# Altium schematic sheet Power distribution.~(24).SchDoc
size A3; SheetNumber: 4; SheetTotal: 7
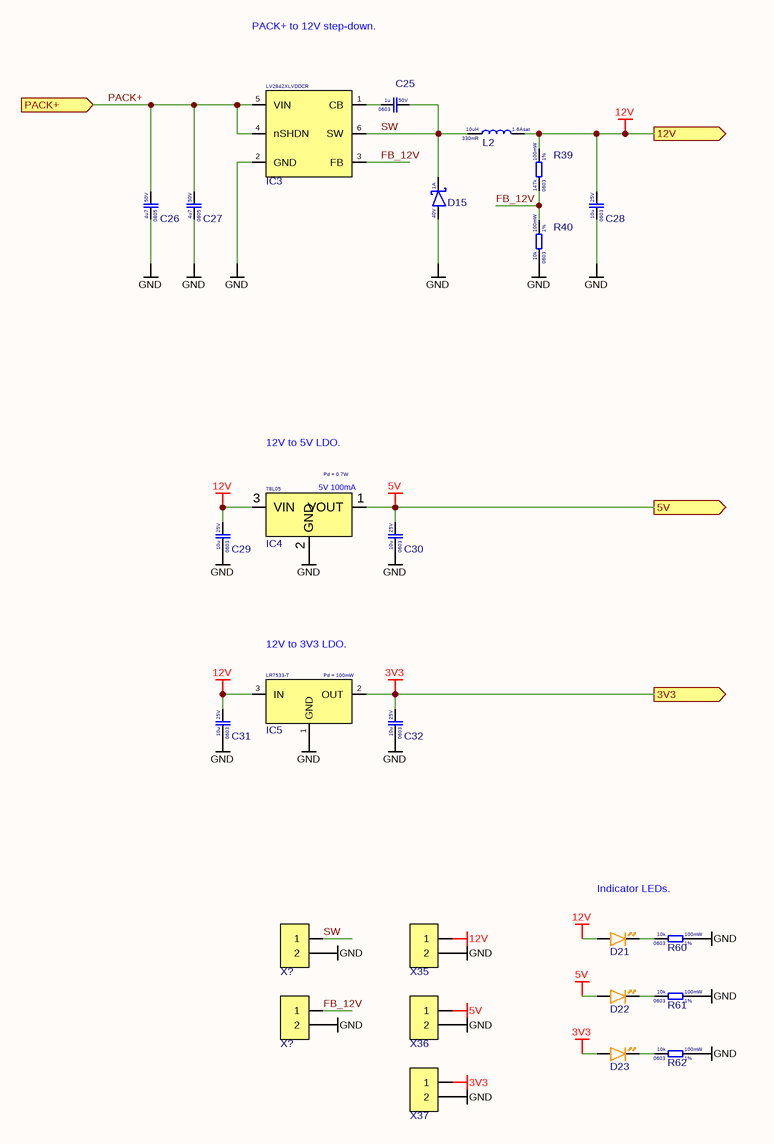
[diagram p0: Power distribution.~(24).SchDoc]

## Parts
(Parts that share a designator on the sheet are numbered #1, #2 ... from top to bottom, then left to right.)
C25  Voltage Rating: 50V  Case Code (Imperial): 0603  Capacitance: 1u  [CAP 0603]  (hidden comment: CL10A105KB8NNNC)
C26  Voltage Rating: 50V  Case Code (Imperial): 0805  Capacitance: 4u7  [Cap_0805]  (hidden comment: CL21A475KBQNNNE)
C27  Voltage Rating: 50V  Case Code (Imperial): 0805  Capacitance: 4u7  [Cap_0805]  (hidden comment: CL21A475KBQNNNE)
C28  Voltage Rating: 25V  Case Code (Imperial): 0603  Capacitance: 10u  [CAP 0603]  (hidden comment: CL10A106MA8NRNC)
C29  Voltage Rating: 25V  Case Code (Imperial): 0603  Capacitance: 10u  [CAP 0603]  (hidden comment: CL10A106MA8NRNC)
C30  Voltage Rating: 25V  Case Code (Imperial): 0603  Capacitance: 10u  [CAP 0603]  (hidden comment: CL10A106MA8NRNC)
C31  Voltage Rating: 25V  Case Code (Imperial): 0603  Capacitance: 10u  [CAP 0603]  (hidden comment: CL10A106MA8NRNC)
C32  Voltage Rating: 25V  Case Code (Imperial): 0603  Capacitance: 10u  [CAP 0603]  (hidden comment: CL10A106MA8NRNC)
D15  Forward Current: 1A  Reverse Voltage: 40V  [SOD-323]  (hidden comment: 1N5819WS)
D21  XL-1608UOC-06  [DIODE_0603]  (value not drawn)
D22  XL-1608UOC-06  [DIODE_0603]  (value not drawn)
D23  XL-1608UOC-06  [DIODE_0603]  (value not drawn)
IC3  LV2842XLVDDCR  [SOT-23-6]
IC4  Pd = 0.7W  [SOT-89-3]
IC5  Pd = 100mW  [SOT-23 123]
L2  Resistance: 330mR  Saturation current: 1.6Asat  Inductance: 10uH  [IND 1008]  (hidden comment: FTC252012S100MBCA)
R39  Resistance Tolerance: 1%  Resistance: 147k  Power Rating: 100mW  Case Code (Imperial): 0603  [RES_0603]  (hidden comment: 0603WAF1473T5E)
R40  Resistance Tolerance: 1%  Resistance: 10k  Power Rating: 100mW  Case Code (Imperial): 0603  [RES_0603]  (hidden comment: 0603WAF1002T5E)
R60  Resistance Tolerance: 1%  Resistance: 10k  Power Rating: 100mW  Case Code (Imperial): 0603  [RES_0603]  (hidden comment: 0603WAF1002T5E)
R61  Resistance Tolerance: 1%  Resistance: 10k  Power Rating: 100mW  Case Code (Imperial): 0603  [RES_0603]  (hidden comment: 0603WAF1002T5E)
R62  Resistance Tolerance: 1%  Resistance: 10k  Power Rating: 100mW  Case Code (Imperial): 0603  [RES_0603]  (hidden comment: 0603WAF1002T5E)
X35  ZX-PZ1.27-1-2PZZ  [Pin header 1x2 1.27mmP THT Vertical]  (value not drawn)
X36  ZX-PZ1.27-1-2PZZ  [Pin header 1x2 1.27mmP THT Vertical]  (value not drawn)
X37  ZX-PZ1.27-1-2PZZ  [Pin header 1x2 1.27mmP THT Vertical]  (value not drawn)
X?#1  ZX-PZ1.27-1-2PZZ  [Pin header 1x2 1.27mmP THT Vertical]  (value not drawn)
X?#2  ZX-PZ1.27-1-2PZZ  [Pin header 1x2 1.27mmP THT Vertical]  (value not drawn)

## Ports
3V3 (out, see Arhitecture[5C], USB PD[3B]), 5V (out, see Arhitecture[5C], USB PD[6B]), 12V (out, see Arhitecture[5C], Charger[1A]), PACK+ (in, see Arhitecture[6C], Battery level indicator[3B], Charger[8A])

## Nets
3V3: C32.2 D23.A IC5.2(OUT) X37.1 ; port 3V3
5V: C30.2 D22.A IC4.1(VOUT) X36.1 ; port 5V
12V: C28.2 C29.2 C31.2 D21.A IC4.3(VIN) IC5.3(IN) L2.2 R39.2 X35.1 ; port 12V
GND: C26.1 C27.1 C28.1 C29.1 C30.1 C31.1 C32.1 D15.A IC3.2(GND) IC4.2(GND) IC5.1(GND) R40.1 R60.2 R61.2 R62.2 X35.2 X36.2 X37.2 X?#1.2 X?#2.2
FB_12V: IC3.3(FB) R39.1 R40.2 X?#2.1
PACK+: C26.2 C27.2 IC3.4(nSHDN) IC3.5(VIN) ; port PACK+
SW: C25.2 D15.K IC3.6(SW) L2.1 X?#1.1
NetC25_1: C25.1 IC3.1(CB)
NetD21_K: D21.K R60.1
NetD22_K: D22.K R61.1
NetD23_K: D23.K R62.1

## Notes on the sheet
- PACK+ to 12V step-down.
- 12V to 5V LDO.
- (near IC5) 12V to 3V3 LDO.
- Indicator LEDs.

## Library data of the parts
C25 = CL10A105KB8NNNC: Cap 1uF 50V 0603 X5R; Manufacturer: Samsung
C26 C27 = CL21A475KBQNNNE: Cap 4.7uF 50V 0805 X5R; Manufacturer: Samsung
C28-C32 = CL10A106MA8NRNC: Cap 10uF 25V 0603 X5R; Manufacturer: Samsung
D15 = 1N5819WS: Schottky 40V 1A 600mVf SOD-323; Manufacturer: Guangdong Hottech
D21-D23 = XL-1608UOC-06: LED Orange 0603 20mA; Manufacturer: XINGLIGHT
IC3 = LV2842XLVDDCR: Step-down converter 4~40Vin 600mAout Adjustible SOT23-6; Manufacturer: Texas Instruments
IC4 = 78L05: LDO 5V 100mA 30Vin; Manufacturer: UMW
IC5 = LR7533-T: LDO 24Vin 3.3Vout fixed; Manufacturer: LR
L2 = FTC252012S100MBCA: Inductor 10uH 1.6Asat 330mR; Manufacturer: cjiang
R39 = 0603WAF1473T5E: Res 147k 0603 1% 100mW 75V; Manufacturer: Uni-Royal
R40 R60-R62 = 0603WAF1002T5E: Res 10k 0603 1% 100mW 75V; Manufacturer: Uni-Royal
X35-X37 X?#1 X?#2 = ZX-PZ1.27-1-2PZZ: Pin header 1x2 1.27mmP THT Vertical; Manufacturer: Megastar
